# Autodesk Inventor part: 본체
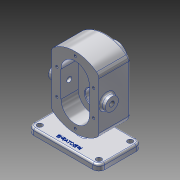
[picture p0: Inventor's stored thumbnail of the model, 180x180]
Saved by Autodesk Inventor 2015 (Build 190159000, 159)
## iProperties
Created: 2019-03
Part Number: 본체
Material: 알루미늄 6061
Document SubType Name: Modeling
Designer: Administrator
Density: 2.7 g/cm^3
Appearance: 알루미늄 - 평지
Mass: 1187.15 g
Surface Area: 719.185 cm^2
Volume: 439.684 cm^3
Author: Administrator
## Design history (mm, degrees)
sketch "스케치1"
  geometry: L1 (-60, 36.5)-(60, 36.5); L2 (60, 36.5)-(60, -36.5); L3 (60, -36.5)-(-60, -36.5); L4 (-60, -36.5)-(-60, 36.5); L5 (-60, 36.5)-(60, -36.5); L6 (60, 36.5)-(-60, -36.5); 1 further point
  constraints: 12 end point, 2 midpoint, 2 parallel, 1 horizontal, 1 perpendicular
  dimensions: "d0" = 120 distance of L2.end L3.end; "d1" = 73 distance of L1.end L2.end
extrude "돌출1" new body sketch "스케치1" distance "d2" = 10; taper "d3" = 0 deg
node "작업 평면1"
sketch "스케치13"
  geometry: L1 (60, 0)-(60, 78); L2 (100, 38)-(100, 118); L3 (20, 38)-(20, 118); A1 r 60 centre (60, 78) between (96, 126) and (24, 126); A2 r 60 centre (60, 78) between (24, 30) and (96, 30); A3 r 10 centre (90, 118) between (100, 118) and (96, 126); A4 r 10 centre (30, 118) between (24, 126) and (20, 118); A5 r 10 centre (30, 38) between (20, 38) and (24, 30); A6 r 10 centre (90, 38) between (96, 30) and (100, 38); 4 further points
  constraints: 16 point on circle, 8 tangent, 6 centre point, 6 end point, 4 point on line, 3 equal radius, 2 parallel, 1 coincident, 1 vertical
  dimensions: "d38" = 78 distance of L1.start L1.end; "d40" = 40 distance between parallel lines of L1 L2; "d41" = 40 distance between parallel lines of L1 L3; "d42" = 60 radius of A1; "d43" = 60 radius of A2; "d44" = 10 radius of A3
extrude "돌출8" join sketch "스케치13" distance "d45" = 53; taper "d46" = 0 deg
sketch "스케치14"
  geometry: L1 (-60, 78)-(-60, 100); L2 (-60, 78)-(-60, 56); L3 (-60, 100)-(-84, 100); L4 (-60, 56)-(-36, 56); L5 (-84, 100)-(-84, 56); L6 (-36, 56)-(-36, 100); A1 r 60 centre (-60, 78) between (-96, 30) and (-24, 30) reference; A2 r 24 centre (-60, 100) between (-36, 100) and (-84, 100); A3 r 24 centre (-60, 56) between (-84, 56) and (-36, 56); 1 further point
  constraints: 12 end point, 4 point on circle, 2 centre point, 2 coincident, 2 point on line, 1 horizontal, 1 parallel, 1 perpendicular, 1 vertical
  dimensions: "d47" = 22 distance of L1.start L1.end; "d48" = 22 distance of L1.start L2.end; "d49" = 24 radius of A2; "d50" = 24 radius of A3
extrude "돌출9" cut sketch "스케치14" distance "d51" = 29; taper "d52" = 0 deg
sketch "스케치15"
  geometry: L1 (-60, 78)-(-60, 100); L2 (-60, 78)-(-60, 56); C1 r 12.5 at (-60, 56); A1 r 60 centre (-60, 78) between (-24, 126) and (-96, 126) reference; 1 further point
  constraints: 4 end point, 1 centre point, 1 coincident, 1 point on line, 1 vertical
  dimensions: "d53" = 22 distance of L1.start L1.end; "d54" = 22 distance of L1.start L2.end; "d55" = 25 diameter of C1
extrude "돌출10" cut sketch "스케치15" distance "d56" = 15; taper "d57" = 0 deg
sketch "스케치16"
  geometry: L1 (-60, 78)-(-60, 100); C1 r 12.5 at (-60, 100); A1 r 60 centre (-60, 78) between (-24, 126) and (-96, 126) reference; 1 further point
  constraints: 2 end point, 1 centre point, 1 coincident, 1 vertical
  dimensions: "d58" = 22 distance of L1.start L1.end; "d59" = 25 diameter of C1
extrude "돌출11" cut sketch "스케치16" distance "d60" = 15; taper "d61" = 0 deg
sketch "스케치17"
  geometry: L1 (60, 78)-(60, 100); C1 r 19 at (60, 100); A1 r 60 centre (60, 78) between (96, 126) and (24, 126) reference; 1 further point
  constraints: 2 end point, 1 centre point, 1 coincident, 1 vertical
  dimensions: "d62" = 22 distance of L1.start L1.end; "d63" = 38 diameter of C1
extrude "돌출12" join sketch "스케치17" distance "d64" = 17; taper "d65" = 0 deg
sketch "스케치18"
  geometry: C1 r 19 at (0, 0) reference; C2 r 14 at (0, 0); 1 further point
  constraints: 1 centre point, 1 coincident
  dimensions: "d66" = 28 diameter of C2
extrude "돌출13" cut sketch "스케치18" distance "d67" = 7.3; taper "d68" = 0 deg
sketch "스케치20"
  geometry: L1 (10, -36.5)-(20, -36.5); L2 (20, -36.5)-(20, 6.5); L3 (20, 6.5)-(10, 6.5); L4 (10, 6.5)-(10, -36.5); 1 further point
  constraints: 8 end point, 2 parallel, 1 horizontal, 1 perpendicular
  dimensions: "d69" = 10 distance of L3.end L2.end; "d70" = 43 distance of L2.end L1.end
extrude "돌출14" join sketch "스케치20" stored distance "d71" = 12; taper "d72" = 0 deg
fillet "모깎기2" dims "d73" = 10
sketch "스케치23"
  geometry: C1 r 4.5 at (-50, -26.5); C2 r 4.5 at (-50, 26.5); C3 r 4.5 at (50, -26.5); C4 r 4.5 at (50, 26.5); A1 r 10 centre (-50, -26.5) between (-60, -26.5) and (-50, -36.5) reference; A2 r 10 centre (-50, 26.5) between (-50, 36.5) and (-60, 26.5) reference; A3 r 10 centre (50, -26.5) between (50, -36.5) and (60, -26.5) reference; A4 r 10 centre (50, 26.5) between (60, 26.5) and (50, 36.5) reference; 1 further point
  constraints: 4 centre point, 4 coincident
  dimensions: "d74" = 9 diameter of C1; "d75" = 9 diameter of C2; "d76" = 9 diameter of C3; "d77" = 9 diameter of C4
extrude "돌출15" cut sketch "스케치23" distance "d78" = 10; taper "d79" = 0 deg
fillet "모깎기3" dims "d80" = 3
fillet "모깎기4" dims "d81" = 3
fillet "모깎기5" dims "d82" = 3
sketch "스케치26"
  geometry: L1 (-60, 100)-(-60, 56); L2 (-60, 100)-(-91, 100); L3 (-60, 56)-(-29, 56); L4 (-91, 100)-(-91, 56); L5 (-29, 56)-(-29, 100); L6 (-60, 100)-(-60, 131); L7 (-60, 56)-(-60, 25); L8 (-60, 56)-(-91, 56); L9 (-60, 100)-(-29, 100); C1 r 12.5 at (-60, 100) reference; C2 r 12.5 at (-60, 56) reference; A1 r 31 centre (-60, 100) between (-29, 100) and (-91, 100); A2 r 31 centre (-60, 56) between (-91, 56) and (-29, 56); 1 further point
  constraints: 18 end point, 6 point on circle, 2 centre point, 2 coincident, 2 parallel, 1 horizontal, 1 tangent, 1 vertical
  dimensions: "d83" = 31 radius of A1; "d84" = 44 distance of L1.start L1.end; "d85" = 31 radius of A2
hole "구멍1" sketch "스케치26" at (-60, 131), (-91, 100), (-29, 100), (-29, 56), (-60, 25), (-91, 56) diameter "d86" = 4.134; stored, may be unused: countersink angle "d90" = 90 deg, drill point angle "d92" = 118 deg; dims "d87" = 10, "d88" = 4, "d89" = 2, "d91" = 12
chamfer "모따기1" distance "d93" = 0.7; stored, may be unused: second distance "d94" = 2, angle "d95" = 30 deg
sketch "스케치31"
  geometry: L1 (0, 62)-(0, 18) reference; L2 (0, 40)-(-14, 40); C1 r 11 at (-14, 40); 1 further point
  constraints: 2 end point, 1 centre point, 1 coincident, 1 horizontal, 1 midpoint
  dimensions: "d106" = 14 distance of L2.start L2.end; "d107" = 22 diameter of C1
extrude "돌출18" join sketch "스케치31" distance "d108" = 8; taper "d109" = 0 deg
sketch "스케치32"
  geometry: L1 (0, 62)-(0, 18) reference; L2 (0, 40)-(14, 40); C1 r 11 at (14, 40) reference; C2 r 11 at (14, 40); 1 further point
  constraints: 2 end point, 1 centre point, 1 coincident, 1 horizontal, 1 midpoint
  dimensions: "d110" = 14 distance of L2.start L2.end (derived); "d111" = 22 diameter of C2
extrude "돌출19" join sketch "스케치32" distance "d112" = 8; taper "d113" = 0 deg
fillet "모깎기6" dims "d114" = 3
sketch "스케치33"
  geometry: C1 r 11 at (0, 0) reference; 2 further points
  constraints: 1 coincident
hole "구멍2" sketch "스케치33" at (0, 0) diameter "d115" = 8.376; stored, may be unused: countersink angle "d119" = 90 deg, drill point angle "d121" = 0 deg; dims "d116" = 20, "d117" = 4, "d118" = 2, "d120" = 14.2
sketch "스케치34"
  geometry: C1 r 11 at (0, 0) reference; 2 further points
  constraints: 1 coincident
hole "구멍3" sketch "스케치34" at (0, 0) diameter "d122" = 8.376; stored, may be unused: countersink angle "d126" = 90 deg, drill point angle "d128" = 0 deg; dims "d123" = 20, "d124" = 4, "d125" = 2, "d127" = 27.3
sketch "스케치35"
  geometry: C1 r 12.5 at (0, 0) reference; C2 r 8.5 at (0, 0); 1 further point
  constraints: 1 centre point, 1 coincident
  dimensions: "d129" = 17 diameter of C2
extrude "돌출20" cut sketch "스케치35" distance "d130" = 19; taper "d131" = 0 deg
chamfer "모따기2" distance "d132" = 1; stored, may be unused: second distance "d133" = 2, angle "d134" = 30 deg
fillet "모깎기7" dims "d135" = 0.7
sketch "스케치37"
  geometry: L1 (-60, -26.5)-(0, -26.5); L2 (-57, -26.5)-(-60, -26.5) reference; 2 further points
  constraints: 2 end point, 1 coincident, 1 collinear, 1 other
  dimensions: "d136" = 60 distance of L1.start L1.end
feature "엠보싱1" sketch "스케치37" dims "d0" = 120, "d1" = 73, "d137" = 0.5, "d138" = 0
fillet "모깎기8" dims "d139" = 3
fillet "모깎기9" dims "d140" = 3
node "솔리드1"
other parameters: "d37" = -53
